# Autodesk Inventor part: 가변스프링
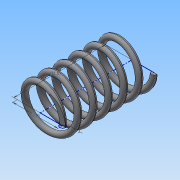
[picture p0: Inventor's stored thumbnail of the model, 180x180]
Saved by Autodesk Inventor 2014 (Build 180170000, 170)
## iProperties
Created: 2018-07
Part Number: 가변스프링
Material: 일반
Document SubType Name: Modeling
Designer: 학생용
Density: 1 g/cm^3
Appearance: 기본값
Mass: 0.935079 g
Surface Area: 18.9541 cm^2
Volume: 0.935079 cm^3
Author: 학생용
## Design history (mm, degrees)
sketch "스케치1"
  geometry: L1 (0, 0)-(8, 0); L2 (8, 32.5)-(0, 32.5); L3 (0, 32.5)-(0, 0); C1 r 1 at (8, 0); 1 further point
  constraints: 6 end point, 2 coincident, 1 centre point, 1 horizontal, 1 parallel, 1 vertical, 1 vertical alignment
  dimensions: "d0" = 2 diameter of C1; "d1" = 16 diameter of L1.end L3; "d15" = 32.5 distance between parallel lines of L1 L2 (derived)
feature "코일1" sketch "스케치1" pitch "d3" = 10; turns "d5" = 6; dims "d4" = 32.5 (= d15), "d6" = 0, angle "d7" = 90 deg, angle "d8" = 90 deg, "d9" = 0, "d10" = 0
node "작업 평면1"
sketch "스케치2"
  geometry: C1 r 16.289 at (0, 0); 1 further point
  constraints: 1 centre point, 1 coincident
extrude "돌출1" cut sketch "스케치2" distance "d11" = 10; taper "d12" = 0 deg
node "작업 평면2"
sketch "스케치3"
  geometry: C1 r 15.26 at (0, 0); 1 further point
  constraints: 1 centre point, 1 coincident
extrude "돌출2" cut sketch "스케치3" distance "d13" = 10; taper "d14" = 0 deg
node "솔리드1"
other parameters: "d2" = 39.5 (derived)
